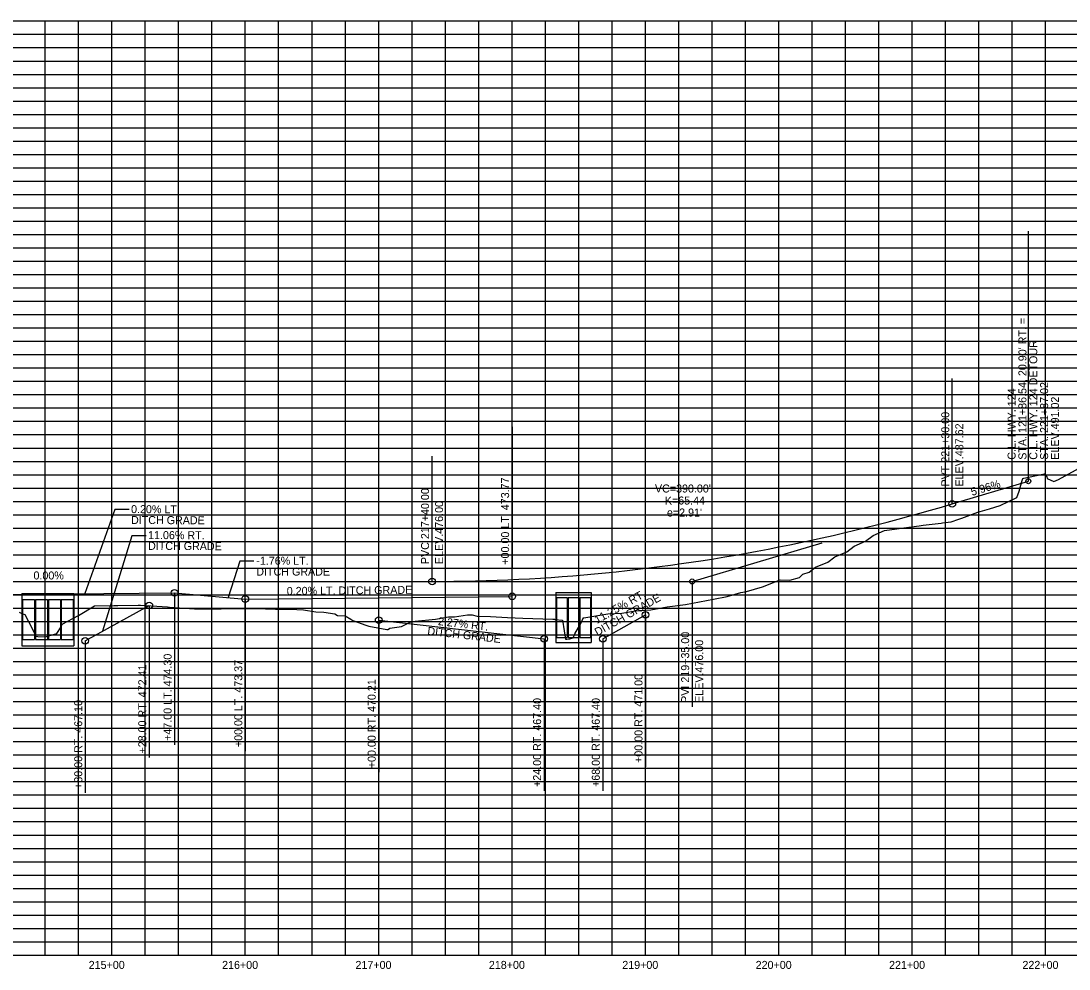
# Model space of a CAD drawing. Extents: x 1054002 to 1056762, y 395173 to 397393.
# Drawn here: x 1055464 to 1056250, y 395173 to 395883 of the extents above; entities that cross this region are included whole.
import ezdxf

# ---------------------------------------------------------------- set-up
doc = ezdxf.new("R2010")
doc.units = 0
for name, color, linetype in [('R_Axis_Annotation', 7, 'Continuous'), ('R_Drainage', 7, 'Continuous'), ('R_Exist Surface', 7, 'Continuous'), ('R_Grid', 7, 'Continuous'), ('R_Grid_Minor', 7, 'Continuous'), ('R_Vert Alg', 7, 'Continuous'), ('R_Vert Alg Annot', 7, 'Continuous')]:
    doc.layers.add(name, color=color, linetype=linetype)

msp = doc.modelspace()

# ---------------------------------------------------------------- linework, layer by layer
at = {"layer": 'R_Drainage'}
for p, q in [((1055464.75, 395454.45), (1055503.83, 395454.45)), ((1055464.75, 395454.45), (1055464.75, 395415.28)), ((1055503.83, 395454.45), (1055503.83, 395415.28)), ((1055865.04, 395455.06), (1055891.54, 395455.06)), ((1055865.04, 395455.06), (1055865.04, 395417.56)), ((1055891.54, 395455.06), (1055891.54, 395417.56)), ((1055465.29, 395449.86), (1055465.29, 395419.86)), ((1055465.29, 395449.86), (1055474.29, 395449.86)), ((1055474.29, 395449.86), (1055474.29, 395419.86)), ((1055474.96, 395449.86), (1055474.96, 395419.86)), ((1055474.96, 395449.86), (1055483.96, 395449.86)), ((1055483.96, 395449.86), (1055483.96, 395419.86)), ((1055484.63, 395449.86), (1055484.63, 395419.86)), ((1055484.63, 395449.86), (1055493.63, 395449.86)), ((1055493.63, 395449.86), (1055493.63, 395419.86)), ((1055494.29, 395449.86), (1055494.29, 395419.86)), ((1055494.29, 395449.86), (1055503.29, 395449.86)), ((1055503.29, 395449.86), (1055503.29, 395419.86)), ((1055865.63, 395451.31), (1055865.63, 395421.31)), ((1055865.63, 395451.31), (1055873.63, 395451.31)), ((1055873.63, 395451.31), (1055873.63, 395421.31)), ((1055874.29, 395451.31), (1055874.29, 395421.31)), ((1055874.29, 395451.31), (1055882.29, 395451.31)), ((1055882.29, 395451.31), (1055882.29, 395421.31)), ((1055882.96, 395451.31), (1055882.96, 395421.31)), ((1055882.96, 395451.31), (1055890.96, 395451.31)), ((1055890.96, 395451.31), (1055890.96, 395421.31)), ((1055865.63, 395421.31), (1055873.63, 395421.31)), ((1055874.29, 395421.31), (1055882.29, 395421.31)), ((1055882.96, 395421.31), (1055890.96, 395421.31)), ((1055464.75, 395415.28), (1055503.83, 395415.28)), ((1055465.29, 395419.86), (1055474.29, 395419.86)), ((1055474.96, 395419.86), (1055483.96, 395419.86)), ((1055483.96, 395419.86), (1055484.63, 395419.86)), ((1055484.63, 395419.86), (1055493.63, 395419.86)), ((1055494.29, 395419.86), (1055503.29, 395419.86)), ((1055865.04, 395417.56), (1055891.54, 395417.56))]:
    msp.add_line(p, q, dxfattribs=at)
at = {"layer": 'R_Exist Surface'}
msp.add_lwpolyline([(1055462.67, 395440.34), (1055464.66, 395439.48), (1055466.89, 395438.62), (1055466.92, 395438.62), (1055473.1, 395427.26), (1055474.37, 395424.42), (1055474.58, 395422.64), (1055476.68, 395422.1), (1055482.14, 395421.82), (1055488.53, 395423.75), (1055491.1, 395424.39), (1055494.24, 395429.52), (1055494.92, 395431.51), (1055507.26, 395438), (1055519.27, 395445.2), (1055533.78, 395445.44), (1055536.61, 395445.41), (1055551.98, 395445.7), (1055552.91, 395445.63), (1055553.82, 395445.56), (1055573.91, 395444.3), (1055575.58, 395444.17), (1055594.17, 395442.99), (1055596.52, 395442.81), (1055598.8, 395442.84), (1055611.84, 395442.97), (1055614.2, 395443), (1055627.13, 395443.12), (1055629.58, 395443.15), (1055647.33, 395442.9), (1055650.89, 395442.96), (1055654.86, 395442.71), (1055670.92, 395442.46), (1055675.87, 395442.14), (1055685.22, 395440.77), (1055691.15, 395440.39), (1055699.49, 395439.24), (1055701.47, 395438.02), (1055707.15, 395437.67), (1055711.3, 395435.18), (1055712.95, 395434.18), (1055722.56, 395430.72), (1055724.93, 395429.89), (1055738.35, 395427.5), (1055739.49, 395427.45), (1055739.68, 395427.6), (1055740.57, 395428.31), (1055749.4, 395429.57), (1055754.82, 395432.48), (1055755.58, 395432.84), (1055759.69, 395433.61), (1055774.95, 395435.16), (1055784.7, 395436.81), (1055789.04, 395436.85), (1055798.87, 395438.43), (1055802.26, 395438.36), (1055806.1, 395437.43), (1055816.15, 395437.1), (1055828.81, 395436.28), (1055840.41, 395435.88), (1055862.94, 395435.11), (1055864.17, 395435.04), (1055864.38, 395434.93), (1055870.02, 395434.32), (1055871.33, 395426.4), (1055872.33, 395420.13), (1055873.29, 395420.15), (1055875.66, 395420.29), (1055876.25, 395420.54), (1055877.97, 395421.23), (1055879.38, 395424.21), (1055883.75, 395432.01), (1055885.89, 395436.44), (1055885.97, 395436.24), (1055904.17, 395439.04), (1055914.48, 395439.68), (1055924.76, 395441.33), (1055936.38, 395442.08), (1055948.44, 395444.38), (1055962.26, 395446.04), (1055962.3, 395446.04), (1055972.8, 395448.1), (1055983.19, 395450.14), (1055993.48, 395452.15), (1056003.7, 395455.02), (1056008.02, 395455.9), (1056020.01, 395459.27), (1056033.3, 395464.68), (1056040.57, 395464.32), (1056047.84, 395466.38), (1056050.31, 395468.87), (1056054.98, 395470.25), (1056059.79, 395474.15), (1056069.06, 395477.8), (1056074.25, 395481.87), (1056083.16, 395485.61), (1056088.63, 395489.79), (1056097.25, 395493.58), (1056102.96, 395497.85), (1056111.36, 395501.68), (1056120.76, 395502.86), (1056125.88, 395503.68), (1056137.49, 395505.08), (1056140.4, 395505.52), (1056154.03, 395507.12), (1056154.9, 395507.25), (1056161.58, 395508), (1056167.15, 395510), (1056169.52, 395510.82), (1056181.54, 395515.34), (1056190.24, 395517.94), (1056198.31, 395520.35), (1056210.57, 395526.42), (1056212.53, 395531.15), (1056214.35, 395538.36), (1056215.24, 395540.51), (1056215.83, 395540.89), (1056229.02, 395543.58), (1056231.26, 395544.18), (1056231.44, 395544.1), (1056233.14, 395541.72), (1056233.43, 395540.5), (1056238.33, 395538.2), (1056241.81, 395539.85), (1056259.67, 395549.45)], dxfattribs=at)
at = {"layer": 'R_Grid'}
for p, q in [((1054032.29, 395883.41), (1056732.29, 395883.41)), ((1054032.29, 395883.41), (1056732.29, 395883.41)), ((1055532.29, 395183.41), (1055532.29, 395883.41)), ((1055632.29, 395183.41), (1055632.29, 395883.41)), ((1055732.29, 395183.41), (1055732.29, 395883.41)), ((1055832.29, 395183.41), (1055832.29, 395883.41)), ((1055932.29, 395183.41), (1055932.29, 395883.41)), ((1056032.29, 395183.41), (1056032.29, 395883.41)), ((1056132.29, 395183.41), (1056132.29, 395883.41)), ((1056232.29, 395183.41), (1056232.29, 395883.41)), ((1054032.29, 395833.41), (1056732.29, 395833.41)), ((1054032.29, 395783.41), (1056732.29, 395783.41)), ((1054032.29, 395733.41), (1056732.29, 395733.41)), ((1054032.29, 395683.41), (1056732.29, 395683.41)), ((1054032.29, 395633.41), (1056732.29, 395633.41)), ((1054032.29, 395583.41), (1056732.29, 395583.41)), ((1054032.29, 395533.41), (1056732.29, 395533.41)), ((1054032.29, 395483.41), (1056732.29, 395483.41)), ((1054032.29, 395433.41), (1056732.29, 395433.41)), ((1054032.29, 395383.41), (1056732.29, 395383.41)), ((1054032.29, 395333.41), (1056732.29, 395333.41)), ((1054032.29, 395283.41), (1056732.29, 395283.41)), ((1054032.29, 395233.41), (1056732.29, 395233.41)), ((1054032.29, 395183.41), (1056732.29, 395183.41))]:
    msp.add_line(p, q, dxfattribs=at)
at = {"layer": 'R_Grid_Minor'}
for p, q in [((1055482.29, 395183.41), (1055482.29, 395883.41)), ((1055507.29, 395183.41), (1055507.29, 395883.41)), ((1055557.29, 395183.41), (1055557.29, 395883.41)), ((1055582.29, 395183.41), (1055582.29, 395883.41)), ((1055607.29, 395183.41), (1055607.29, 395883.41)), ((1055657.29, 395183.41), (1055657.29, 395883.41)), ((1055682.29, 395183.41), (1055682.29, 395883.41)), ((1055707.29, 395183.41), (1055707.29, 395883.41)), ((1055757.29, 395183.41), (1055757.29, 395883.41)), ((1055782.29, 395183.41), (1055782.29, 395883.41)), ((1055807.29, 395183.41), (1055807.29, 395883.41)), ((1055857.29, 395183.41), (1055857.29, 395883.41)), ((1055882.29, 395183.41), (1055882.29, 395883.41)), ((1055907.29, 395183.41), (1055907.29, 395883.41)), ((1055957.29, 395183.41), (1055957.29, 395883.41)), ((1055982.29, 395183.41), (1055982.29, 395883.41)), ((1056007.29, 395183.41), (1056007.29, 395883.41)), ((1056057.29, 395183.41), (1056057.29, 395883.41)), ((1056082.29, 395183.41), (1056082.29, 395883.41)), ((1056107.29, 395183.41), (1056107.29, 395883.41)), ((1056157.29, 395183.41), (1056157.29, 395883.41)), ((1056182.29, 395183.41), (1056182.29, 395883.41)), ((1056207.29, 395183.41), (1056207.29, 395883.41)), ((1054032.29, 395873.41), (1056732.29, 395873.41)), ((1054032.29, 395863.41), (1056732.29, 395863.41)), ((1054032.29, 395853.41), (1056732.29, 395853.41)), ((1054032.29, 395843.41), (1056732.29, 395843.41)), ((1054032.29, 395823.41), (1056732.29, 395823.41)), ((1054032.29, 395813.41), (1056732.29, 395813.41)), ((1054032.29, 395803.41), (1056732.29, 395803.41)), ((1054032.29, 395793.41), (1056732.29, 395793.41)), ((1054032.29, 395773.41), (1056732.29, 395773.41)), ((1054032.29, 395763.41), (1056732.29, 395763.41)), ((1054032.29, 395753.41), (1056732.29, 395753.41)), ((1054032.29, 395743.41), (1056732.29, 395743.41)), ((1054032.29, 395723.41), (1056732.29, 395723.41)), ((1054032.29, 395713.41), (1056732.29, 395713.41)), ((1054032.29, 395703.41), (1056732.29, 395703.41)), ((1054032.29, 395693.41), (1056732.29, 395693.41)), ((1054032.29, 395673.41), (1056732.29, 395673.41)), ((1054032.29, 395663.41), (1056732.29, 395663.41)), ((1054032.29, 395653.41), (1056732.29, 395653.41)), ((1054032.29, 395643.41), (1056732.29, 395643.41)), ((1054032.29, 395623.41), (1056732.29, 395623.41)), ((1054032.29, 395613.41), (1056732.29, 395613.41)), ((1054032.29, 395603.41), (1056732.29, 395603.41)), ((1054032.29, 395593.41), (1056732.29, 395593.41)), ((1054032.29, 395573.41), (1056732.29, 395573.41)), ((1054032.29, 395563.41), (1056732.29, 395563.41)), ((1054032.29, 395553.41), (1056732.29, 395553.41)), ((1054032.29, 395543.41), (1056732.29, 395543.41)), ((1054032.29, 395523.41), (1056732.29, 395523.41)), ((1054032.29, 395513.41), (1056732.29, 395513.41)), ((1054032.29, 395503.41), (1056732.29, 395503.41)), ((1054032.29, 395493.41), (1056732.29, 395493.41)), ((1054032.29, 395473.41), (1056732.29, 395473.41)), ((1054032.29, 395463.41), (1056732.29, 395463.41)), ((1054032.29, 395453.41), (1056732.29, 395453.41)), ((1054032.29, 395443.41), (1056732.29, 395443.41)), ((1054032.29, 395423.41), (1056732.29, 395423.41)), ((1054032.29, 395413.41), (1056732.29, 395413.41)), ((1054032.29, 395403.41), (1056732.29, 395403.41)), ((1054032.29, 395393.41), (1056732.29, 395393.41)), ((1054032.29, 395373.41), (1056732.29, 395373.41)), ((1054032.29, 395363.41), (1056732.29, 395363.41)), ((1054032.29, 395353.41), (1056732.29, 395353.41)), ((1054032.29, 395343.41), (1056732.29, 395343.41)), ((1054032.29, 395323.41), (1056732.29, 395323.41)), ((1054032.29, 395313.41), (1056732.29, 395313.41)), ((1054032.29, 395303.41), (1056732.29, 395303.41)), ((1054032.29, 395293.41), (1056732.29, 395293.41)), ((1054032.29, 395273.41), (1056732.29, 395273.41)), ((1054032.29, 395263.41), (1056732.29, 395263.41)), ((1054032.29, 395253.41), (1056732.29, 395253.41)), ((1054032.29, 395243.41), (1056732.29, 395243.41)), ((1054032.29, 395223.41), (1056732.29, 395223.41)), ((1054032.29, 395213.41), (1056732.29, 395213.41)), ((1054032.29, 395203.41), (1056732.29, 395203.41)), ((1054032.29, 395193.41), (1056732.29, 395193.41))]:
    msp.add_line(p, q, dxfattribs=at)
at = {"layer": 'R_Vert Alg'}
for p, q in [((1056162.29, 395521.52), (1056219.31, 395538.51)), ((1055132.29, 395463.41), (1055772.29, 395463.41)), ((1055332.29, 395452.46), (1055579.29, 395454.93)), ((1055579.29, 395454.93), (1055632.29, 395450.26)), ((1055632.29, 395450.26), (1055832.29, 395452.26)), ((1055512.29, 395418.91), (1055560.29, 395445.46)), ((1055900.29, 395420.41), (1055932.29, 395438.41)), ((1055732.29, 395434.46), (1055856.29, 395420.41))]:
    msp.add_line(p, q, dxfattribs=at)
msp.add_lwpolyline([(1055772.29, 395463.41), (1055780.42, 395463.44), (1055788.54, 395463.51), (1055796.67, 395463.64), (1055804.79, 395463.82), (1055812.92, 395464.04), (1055821.04, 395464.32), (1055829.17, 395464.65), (1055837.29, 395465.03), (1055845.42, 395465.46), (1055853.54, 395465.94), (1055861.67, 395466.46), (1055869.79, 395467.04), (1055877.92, 395467.68), (1055886.04, 395468.36), (1055894.17, 395469.09), (1055902.29, 395469.87), (1055910.42, 395470.7), (1055918.54, 395471.58), (1055926.67, 395472.52), (1055934.79, 395473.5), (1055942.92, 395474.54), (1055951.04, 395475.62), (1055959.17, 395476.75), (1055975.42, 395479.18), (1055983.54, 395480.46), (1055991.67, 395481.8), (1055999.79, 395483.19), (1056007.92, 395484.62), (1056016.04, 395486.11), (1056024.17, 395487.65), (1056032.29, 395489.24), (1056040.42, 395490.88), (1056048.54, 395492.57), (1056056.67, 395494.31), (1056064.79, 395496.1), (1056072.92, 395497.94), (1056081.04, 395499.83), (1056089.17, 395501.77), (1056097.29, 395503.77), (1056105.42, 395505.81), (1056113.54, 395507.9), (1056121.67, 395510.05), (1056129.79, 395512.24), (1056137.92, 395514.48), (1056146.04, 395516.78), (1056154.17, 395519.13), (1056162.29, 395521.52)], dxfattribs=at)
at = {"layer": 'R_Vert Alg Annot'}
for p, q in [((1056219.31, 395550.51), (1056219.31, 395725.97)), ((1056162.29, 395531.52), (1056162.29, 395615.52)), ((1055832.29, 395579.24), (1055832.29, 395472.97)), ((1055772.29, 395473.41), (1055772.29, 395557.41)), ((1056219.31, 395538.51), (1056219.31, 395550.51)), ((1056162.29, 395521.52), (1056162.29, 395531.52)), ((1055967.29, 395463.41), (1056064.79, 395492.47)), ((1055772.29, 395463.41), (1055772.29, 395473.41)), ((1055832.29, 395452.26), (1055832.29, 395472.97)), ((1055869.79, 395463.41), (1055967.29, 395463.41)), ((1055967.29, 395463.41), (1055967.29, 395453.41)), ((1055579.29, 395454.93), (1055579.29, 395424.93)), ((1055967.29, 395453.41), (1055967.29, 395369.41)), ((1055560.29, 395445.46), (1055560.29, 395415.46)), ((1055632.29, 395450.26), (1055632.29, 395420.26)), ((1055932.29, 395438.41), (1055932.29, 395408.41)), ((1055932.29, 395438.41), (1055932.29, 395408.41)), ((1055732.29, 395434.46), (1055732.29, 395404.46)), ((1055579.29, 395424.93), (1055579.29, 395340.93)), ((1055856.29, 395420.41), (1055856.29, 395390.41)), ((1055900.29, 395420.41), (1055900.29, 395390.41)), ((1055512.29, 395418.91), (1055512.29, 395388.91)), ((1055560.29, 395415.46), (1055560.29, 395331.46)), ((1055632.29, 395420.26), (1055632.29, 395336.26)), ((1055932.29, 395408.41), (1055932.29, 395324.41)), ((1055932.29, 395408.41), (1055932.29, 395324.41)), ((1055732.29, 395404.46), (1055732.29, 395320.46)), ((1055856.29, 395390.41), (1055856.29, 395306.41)), ((1055900.29, 395390.41), (1055900.29, 395306.41)), ((1055512.29, 395388.91), (1055512.29, 395304.91))]:
    msp.add_line(p, q, dxfattribs=at)
for points in [[(1055545.17, 395517.43), (1055534.53, 395517.4), (1055512.05, 395454.26)], [(1055557.94, 395497.68), (1055547.3, 395497.65), (1055525.27, 395426.09)], [(1055638.78, 395478.61), (1055628.14, 395478.58), (1055619.54, 395451.39)]]:
    msp.add_lwpolyline(points, dxfattribs=at)
for centre, radius in [((1056219.31, 395538.51), 1.85), ((1056162.29, 395521.52), 2.5), ((1055772.29, 395463.41), 2.5), ((1055967.29, 395463.41), 1.85), ((1055579.29, 395454.93), 2.5), ((1055632.29, 395450.26), 2.5), ((1055832.29, 395452.26), 2.5), ((1055560.29, 395445.46), 2.5), ((1055732.29, 395434.46), 2.5), ((1055932.29, 395438.41), 2.5), ((1055932.29, 395438.41), 2.5), ((1055512.29, 395418.91), 2.5), ((1055856.29, 395420.41), 2.5), ((1055900.29, 395420.41), 2.5)]:
    msp.add_circle(centre, radius, dxfattribs=at)

# ---------------------------------------------------------------- texts
at = {"layer": 'R_Axis_Annotation'}
for s, p in [('215+00', (1055514.89, 395173.06)), ('216+00', (1055614.89, 395173.06)), ('217+00', (1055714.89, 395173.06)), ('218+00', (1055814.89, 395173.06)), ('219+00', (1055914.89, 395173.06)), ('220+00', (1056014.89, 395173.06)), ('221+00', (1056114.89, 395173.06)), ('222+00', (1056214.89, 395173.06))]:
    msp.add_text(s, height=6, dxfattribs=at).set_placement(p)
at = {"layer": 'R_Vert Alg Annot'}
for s, rotation, p in [("STA. 121+86.54, 20.90' RT. =", 90, (1056217.88, 395554.61)), ('C.L. HWY. 124 DETOUR', 90, (1056226.01, 395554.61)), ('STA. 221+87.02', 90, (1056234.14, 395554.61)), ('C.L. HWY. 124', 90, (1056209.76, 395554.61)), ('ELEV.491.02', 90, (1056242.26, 395554.61)), ('PVT 221+30.00', 90, (1056160.04, 395534.52)), ('ELEV.487.62', 90, (1056170.54, 395534.52)), ('+00.00 LT. 473.77', 90, (1055830.04, 395475.97)), ('5.96%', 16.59365, (1056177.15, 395527.51)), ('PVC 217+40.00', 90, (1055770.04, 395476.41)), ('ELEV.476.00', 90, (1055780.54, 395476.41)), ('0.20% LT.', 359.73823, (1055546.64, 395514.62)), ('DITCH GRADE', 359.73823, (1055546.6, 395506.49)), ('11.06% RT.', 359.73823, (1055559.4, 395495.2)), ('DITCH GRADE', 359.73823, (1055559.36, 395487.08)), ('-1.76% LT.', 359.97535, (1055640.55, 395475.93)), ('DITCH GRADE', 359.97535, (1055640.54, 395467.8)), ('0.20% LT. DITCH GRADE', 0.57294, (1055663.39, 395453.24)), ('DITCH GRADE', 29.35775, (1055896.22, 395422.32)), ('11.25% RT.', 29.35775, (1055896.05, 395431.55)), ('-2.27% RT.', 353.53559, (1055773.82, 395431.08)), ('DITCH GRADE', 353.53559, (1055768.55, 395423.5)), ('PVI 219+35.00', 90, (1055965.04, 395372.41)), ('ELEV.476.00', 90, (1055975.54, 395372.41)), ('+47.00 LT. 474.30', 90, (1055577.04, 395343.93)), ('+28.00 RT. 472.41', 90, (1055558.04, 395334.46)), ('+00.00 LT. 473.37', 90, (1055630.04, 395339.26)), ('+00.00 RT. 470.21', 90, (1055730.04, 395323.46)), ('+00.00 RT. 471.00', 90, (1055930.04, 395327.41)), ('+00.00 RT. 471.00', 90, (1055930.04, 395327.41)), ('+80.00 RT. 467.10', 90, (1055510.04, 395307.91)), ('+24.00 RT. 467.40', 90, (1055854.04, 395309.41)), ('+68.00 RT. 467.40', 90, (1055898.04, 395309.41))]:
    msp.add_text(s, height=6, rotation=rotation, dxfattribs=at).set_placement(p)
for s, p in [("VC=390.00'", (1055939.39, 395530.07)), ('K=65.44', (1055946.82, 395521.07)), ("e=2.91'", (1055948.39, 395512.07)), ('0.00%', (1055473.49, 395464.91))]:
    msp.add_text(s, height=6, dxfattribs=at).set_placement(p)

doc.saveas('drawing.dxf')
